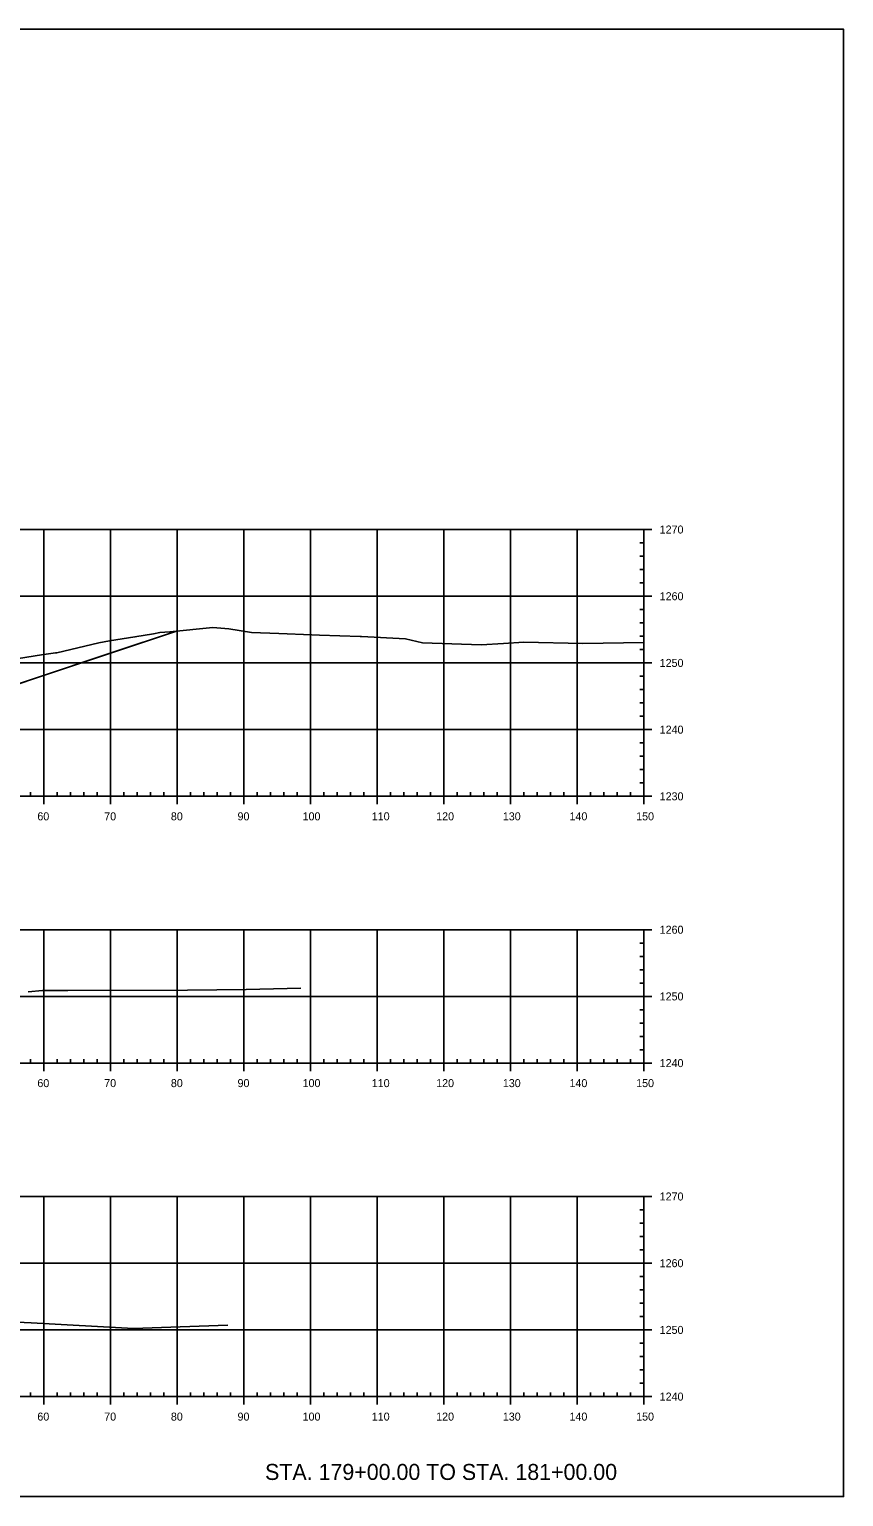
# Model space of a CAD drawing. Extents: x 659657 to 668193, y 633084 to 648639.
# Drawn here: x 667020.3 to 667142.5, y 643502.4 to 643722.4 of the extents above; entities that cross this region are included whole.
import ezdxf

# ---------------------------------------------------------------- set-up
doc = ezdxf.new("R2010")
doc.units = 0
for name, color, linetype in [('Default', 7, 'Continuous'), ('R_Axis', 7, 'Continuous'), ('R_Axis Annot', 7, 'Continuous'), ('R_Exist Surface', 7, 'Continuous'), ('R_Grid', 7, 'Continuous'), ('T_SIGNAL CONTROL CABINET', 7, 'Continuous'), ('TEMP_SIGNAL POLES', 7, 'Continuous'), ('TEMP_SIGNAL_HEAD_STAGE 5', 7, 'Continuous')]:
    doc.layers.add(name, color=color, linetype=linetype)

msp = doc.modelspace()

# ---------------------------------------------------------------- linework, layer by layer
at = {"layer": 'Default'}
for points in [[(666915.04, 643630.48), (666929.59, 643628.06), (666951.01, 643631.63), (666955.01, 643631.3), (666970.01, 643630.05), (666976.01, 643629.55), (667000.01, 643625.55), (667011.31, 643621.79), (667017.29, 643623.78), (667022.62, 643625.56), (667025, 643626.35), (667028.57, 643627.54), (667032.79, 643628.95), (667042.41, 643632.15)], [(666958.62, 643631.58), (666959.01, 643630.8), (666959.01, 643630.97), (666970.01, 643630.05), (666976.01, 643629.55), (667000.01, 643625.55), (667011.31, 643621.79), (667017.29, 643623.78), (667022.62, 643625.56), (667025, 643626.35), (667028.57, 643627.54), (667032.79, 643628.95), (667042.41, 643632.15)]]:
    msp.add_lwpolyline(points, dxfattribs=at)
at = {"layer": 'R_Axis'}
for p, q in [((667113.71, 643647.39), (667111.31, 643647.39)), ((667112.51, 643645.39), (667111.91, 643645.39)), ((667112.51, 643607.39), (667112.51, 643647.39)), ((667112.51, 643643.39), (667111.91, 643643.39)), ((667112.51, 643641.39), (667111.91, 643641.39)), ((667112.51, 643639.39), (667111.91, 643639.39)), ((667113.71, 643637.39), (667111.31, 643637.39)), ((667112.51, 643635.39), (667111.91, 643635.39)), ((667112.51, 643633.39), (667111.91, 643633.39)), ((667112.51, 643631.39), (667111.91, 643631.39)), ((667112.51, 643629.39), (667111.91, 643629.39)), ((667113.71, 643627.39), (667111.31, 643627.39)), ((667112.51, 643625.39), (667111.91, 643625.39)), ((667112.51, 643623.39), (667111.91, 643623.39)), ((667112.51, 643621.39), (667111.91, 643621.39)), ((667112.51, 643619.39), (667111.91, 643619.39)), ((667113.71, 643617.39), (667111.31, 643617.39)), ((667112.51, 643615.39), (667111.91, 643615.39)), ((667112.51, 643613.39), (667111.91, 643613.39)), ((667112.51, 643611.39), (667111.91, 643611.39)), ((667020.51, 643607.39), (667020.51, 643607.99)), ((667022.51, 643606.19), (667022.51, 643608.59)), ((667024.51, 643607.39), (667024.51, 643607.99)), ((667026.51, 643607.39), (667026.51, 643607.99)), ((667028.51, 643607.39), (667028.51, 643607.99)), ((667030.51, 643607.39), (667030.51, 643607.99)), ((667032.51, 643606.19), (667032.51, 643608.59)), ((667034.51, 643607.39), (667034.51, 643607.99)), ((667036.51, 643607.39), (667036.51, 643607.99)), ((667038.51, 643607.39), (667038.51, 643607.99)), ((667040.51, 643607.39), (667040.51, 643607.99)), ((667042.51, 643606.19), (667042.51, 643608.59)), ((667044.51, 643607.39), (667044.51, 643607.99)), ((667046.51, 643607.39), (667046.51, 643607.99)), ((667048.51, 643607.39), (667048.51, 643607.99)), ((667050.51, 643607.39), (667050.51, 643607.99)), ((667052.51, 643606.19), (667052.51, 643608.59)), ((667054.51, 643607.39), (667054.51, 643607.99)), ((667056.51, 643607.39), (667056.51, 643607.99)), ((667058.51, 643607.39), (667058.51, 643607.99)), ((667060.51, 643607.39), (667060.51, 643607.99)), ((667062.51, 643606.19), (667062.51, 643608.59)), ((667064.51, 643607.39), (667064.51, 643607.99)), ((667066.51, 643607.39), (667066.51, 643607.99)), ((667068.51, 643607.39), (667068.51, 643607.99)), ((667070.51, 643607.39), (667070.51, 643607.99)), ((667072.51, 643606.19), (667072.51, 643608.59)), ((667074.51, 643607.39), (667074.51, 643607.99)), ((667076.51, 643607.39), (667076.51, 643607.99)), ((667078.51, 643607.39), (667078.51, 643607.99)), ((667080.51, 643607.39), (667080.51, 643607.99)), ((667082.51, 643606.19), (667082.51, 643608.59)), ((667084.51, 643607.39), (667084.51, 643607.99)), ((667086.51, 643607.39), (667086.51, 643607.99)), ((667088.51, 643607.39), (667088.51, 643607.99)), ((667090.51, 643607.39), (667090.51, 643607.99)), ((667092.51, 643606.19), (667092.51, 643608.59)), ((667094.51, 643607.39), (667094.51, 643607.99)), ((667096.51, 643607.39), (667096.51, 643607.99)), ((667098.51, 643607.39), (667098.51, 643607.99)), ((667100.51, 643607.39), (667100.51, 643607.99)), ((667102.51, 643606.19), (667102.51, 643608.59)), ((667104.51, 643607.39), (667104.51, 643607.99)), ((667106.51, 643607.39), (667106.51, 643607.99)), ((667108.51, 643607.39), (667108.51, 643607.99)), ((667110.51, 643607.39), (667110.51, 643607.99)), ((667112.51, 643609.39), (667111.91, 643609.39)), ((667112.51, 643606.19), (667112.51, 643608.59)), ((666812.51, 643607.39), (667112.51, 643607.39)), ((667113.71, 643607.39), (667111.31, 643607.39)), ((667113.71, 643587.39), (667111.31, 643587.39)), ((667112.51, 643567.39), (667112.51, 643587.39)), ((667112.51, 643585.39), (667111.91, 643585.39)), ((667112.51, 643583.39), (667111.91, 643583.39)), ((667112.51, 643581.39), (667111.91, 643581.39)), ((667112.51, 643579.39), (667111.91, 643579.39)), ((667113.71, 643577.39), (667111.31, 643577.39)), ((667112.51, 643575.39), (667111.91, 643575.39)), ((667112.51, 643573.39), (667111.91, 643573.39)), ((667112.51, 643571.39), (667111.91, 643571.39)), ((667022.51, 643566.19), (667022.51, 643568.59)), ((667032.51, 643566.19), (667032.51, 643568.59)), ((667042.51, 643566.19), (667042.51, 643568.59)), ((667052.51, 643566.19), (667052.51, 643568.59)), ((667062.51, 643566.19), (667062.51, 643568.59)), ((667072.51, 643566.19), (667072.51, 643568.59)), ((667082.51, 643566.19), (667082.51, 643568.59)), ((667092.51, 643566.19), (667092.51, 643568.59)), ((667102.51, 643566.19), (667102.51, 643568.59)), ((667112.51, 643569.39), (667111.91, 643569.39)), ((667112.51, 643566.19), (667112.51, 643568.59)), ((666812.51, 643567.39), (667112.51, 643567.39)), ((667020.51, 643567.39), (667020.51, 643567.99)), ((667024.51, 643567.39), (667024.51, 643567.99)), ((667026.51, 643567.39), (667026.51, 643567.99)), ((667028.51, 643567.39), (667028.51, 643567.99)), ((667030.51, 643567.39), (667030.51, 643567.99)), ((667034.51, 643567.39), (667034.51, 643567.99)), ((667036.51, 643567.39), (667036.51, 643567.99)), ((667038.51, 643567.39), (667038.51, 643567.99)), ((667040.51, 643567.39), (667040.51, 643567.99)), ((667044.51, 643567.39), (667044.51, 643567.99)), ((667046.51, 643567.39), (667046.51, 643567.99)), ((667048.51, 643567.39), (667048.51, 643567.99)), ((667050.51, 643567.39), (667050.51, 643567.99)), ((667054.51, 643567.39), (667054.51, 643567.99)), ((667056.51, 643567.39), (667056.51, 643567.99)), ((667058.51, 643567.39), (667058.51, 643567.99)), ((667060.51, 643567.39), (667060.51, 643567.99)), ((667064.51, 643567.39), (667064.51, 643567.99)), ((667066.51, 643567.39), (667066.51, 643567.99)), ((667068.51, 643567.39), (667068.51, 643567.99)), ((667070.51, 643567.39), (667070.51, 643567.99)), ((667074.51, 643567.39), (667074.51, 643567.99)), ((667076.51, 643567.39), (667076.51, 643567.99)), ((667078.51, 643567.39), (667078.51, 643567.99)), ((667080.51, 643567.39), (667080.51, 643567.99)), ((667084.51, 643567.39), (667084.51, 643567.99)), ((667086.51, 643567.39), (667086.51, 643567.99)), ((667088.51, 643567.39), (667088.51, 643567.99)), ((667090.51, 643567.39), (667090.51, 643567.99)), ((667094.51, 643567.39), (667094.51, 643567.99)), ((667096.51, 643567.39), (667096.51, 643567.99)), ((667098.51, 643567.39), (667098.51, 643567.99)), ((667100.51, 643567.39), (667100.51, 643567.99)), ((667104.51, 643567.39), (667104.51, 643567.99)), ((667106.51, 643567.39), (667106.51, 643567.99)), ((667108.51, 643567.39), (667108.51, 643567.99)), ((667110.51, 643567.39), (667110.51, 643567.99)), ((667113.71, 643567.39), (667111.31, 643567.39)), ((667113.71, 643547.39), (667111.31, 643547.39)), ((667112.51, 643517.39), (667112.51, 643547.39)), ((667112.51, 643545.39), (667111.91, 643545.39)), ((667112.51, 643543.39), (667111.91, 643543.39)), ((667112.51, 643541.39), (667111.91, 643541.39)), ((667112.51, 643539.39), (667111.91, 643539.39)), ((667113.71, 643537.39), (667111.31, 643537.39)), ((667112.51, 643535.39), (667111.91, 643535.39)), ((667112.51, 643533.39), (667111.91, 643533.39)), ((667112.51, 643531.39), (667111.91, 643531.39)), ((667112.51, 643529.39), (667111.91, 643529.39)), ((667113.71, 643527.39), (667111.31, 643527.39)), ((667112.51, 643525.39), (667111.91, 643525.39)), ((667112.51, 643523.39), (667111.91, 643523.39)), ((667112.51, 643521.39), (667111.91, 643521.39)), ((667020.51, 643517.39), (667020.51, 643517.99)), ((667022.51, 643516.19), (667022.51, 643518.59)), ((667024.51, 643517.39), (667024.51, 643517.99)), ((667026.51, 643517.39), (667026.51, 643517.99)), ((667028.51, 643517.39), (667028.51, 643517.99)), ((667030.51, 643517.39), (667030.51, 643517.99)), ((667032.51, 643516.19), (667032.51, 643518.59)), ((667034.51, 643517.39), (667034.51, 643517.99)), ((667036.51, 643517.39), (667036.51, 643517.99)), ((667038.51, 643517.39), (667038.51, 643517.99)), ((667040.51, 643517.39), (667040.51, 643517.99)), ((667042.51, 643516.19), (667042.51, 643518.59)), ((667044.51, 643517.39), (667044.51, 643517.99)), ((667046.51, 643517.39), (667046.51, 643517.99)), ((667048.51, 643517.39), (667048.51, 643517.99)), ((667050.51, 643517.39), (667050.51, 643517.99)), ((667052.51, 643516.19), (667052.51, 643518.59)), ((667054.51, 643517.39), (667054.51, 643517.99)), ((667056.51, 643517.39), (667056.51, 643517.99)), ((667058.51, 643517.39), (667058.51, 643517.99)), ((667060.51, 643517.39), (667060.51, 643517.99)), ((667062.51, 643516.19), (667062.51, 643518.59)), ((667064.51, 643517.39), (667064.51, 643517.99)), ((667066.51, 643517.39), (667066.51, 643517.99)), ((667068.51, 643517.39), (667068.51, 643517.99)), ((667070.51, 643517.39), (667070.51, 643517.99)), ((667072.51, 643516.19), (667072.51, 643518.59)), ((667074.51, 643517.39), (667074.51, 643517.99)), ((667076.51, 643517.39), (667076.51, 643517.99)), ((667078.51, 643517.39), (667078.51, 643517.99)), ((667080.51, 643517.39), (667080.51, 643517.99)), ((667082.51, 643516.19), (667082.51, 643518.59)), ((667084.51, 643517.39), (667084.51, 643517.99)), ((667086.51, 643517.39), (667086.51, 643517.99)), ((667088.51, 643517.39), (667088.51, 643517.99)), ((667090.51, 643517.39), (667090.51, 643517.99)), ((667092.51, 643516.19), (667092.51, 643518.59)), ((667094.51, 643517.39), (667094.51, 643517.99)), ((667096.51, 643517.39), (667096.51, 643517.99)), ((667098.51, 643517.39), (667098.51, 643517.99)), ((667100.51, 643517.39), (667100.51, 643517.99)), ((667102.51, 643516.19), (667102.51, 643518.59)), ((667104.51, 643517.39), (667104.51, 643517.99)), ((667106.51, 643517.39), (667106.51, 643517.99)), ((667108.51, 643517.39), (667108.51, 643517.99)), ((667110.51, 643517.39), (667110.51, 643517.99)), ((667112.51, 643519.39), (667111.91, 643519.39)), ((667112.51, 643516.19), (667112.51, 643518.59)), ((666812.51, 643517.39), (667112.51, 643517.39)), ((667113.71, 643517.39), (667111.31, 643517.39))]:
    msp.add_line(p, q, dxfattribs=at)
at = {"layer": 'R_Exist Surface'}
for points in [[(667008.01, 643626.34), (667022.17, 643628.59), (667024.27, 643628.88), (667024.49, 643628.92), (667030.78, 643630.41), (667032.36, 643630.68), (667036.18, 643631.28), (667038.97, 643631.75), (667039.91, 643631.94), (667041.43, 643632.06), (667047.87, 643632.68), (667050.27, 643632.48), (667053.65, 643631.97), (667057.77, 643631.78), (667062.73, 643631.6), (667063.89, 643631.57), (667069.97, 643631.35), (667070.2, 643631.35), (667076.77, 643631.02), (667079.33, 643630.41), (667088.12, 643630.1), (667091.49, 643630.32), (667094.55, 643630.52), (667103.39, 643630.31), (667112.51, 643630.45)], [(667020.19, 643578.09), (667022.31, 643578.26), (667026.11, 643578.28), (667044.08, 643578.33), (667052.89, 643578.45), (667061.08, 643578.63)], [(667018.54, 643528.56), (667020.62, 643528.43), (667035.97, 643527.6), (667042.99, 643527.85), (667050.1, 643528.12)]]:
    msp.add_lwpolyline(points, dxfattribs=at)
at = {"layer": 'R_Grid'}
for p, q in [((666812.51, 643647.39), (667112.51, 643647.39)), ((667022.51, 643607.39), (667022.51, 643647.39)), ((667032.51, 643607.39), (667032.51, 643647.39)), ((667042.51, 643607.39), (667042.51, 643647.39)), ((667052.51, 643607.39), (667052.51, 643647.39)), ((667062.51, 643607.39), (667062.51, 643647.39)), ((667072.51, 643607.39), (667072.51, 643647.39)), ((667082.51, 643607.39), (667082.51, 643647.39)), ((667092.51, 643607.39), (667092.51, 643647.39)), ((667102.51, 643607.39), (667102.51, 643647.39)), ((667112.51, 643607.39), (667112.51, 643647.39)), ((666812.51, 643637.39), (667112.51, 643637.39)), ((666812.51, 643627.39), (667112.51, 643627.39)), ((666812.51, 643617.39), (667112.51, 643617.39)), ((666812.51, 643607.39), (667112.51, 643607.39)), ((666812.51, 643587.39), (667112.51, 643587.39)), ((667022.51, 643567.39), (667022.51, 643587.39)), ((667032.51, 643567.39), (667032.51, 643587.39)), ((667042.51, 643567.39), (667042.51, 643587.39)), ((667052.51, 643567.39), (667052.51, 643587.39)), ((667062.51, 643567.39), (667062.51, 643587.39)), ((667072.51, 643567.39), (667072.51, 643587.39)), ((667082.51, 643567.39), (667082.51, 643587.39)), ((667092.51, 643567.39), (667092.51, 643587.39)), ((667102.51, 643567.39), (667102.51, 643587.39)), ((667112.51, 643567.39), (667112.51, 643587.39)), ((666812.51, 643577.39), (667112.51, 643577.39)), ((666812.51, 643567.39), (667112.51, 643567.39)), ((666812.51, 643547.39), (667112.51, 643547.39)), ((667022.51, 643517.39), (667022.51, 643547.39)), ((667032.51, 643517.39), (667032.51, 643547.39)), ((667042.51, 643517.39), (667042.51, 643547.39)), ((667052.51, 643517.39), (667052.51, 643547.39)), ((667062.51, 643517.39), (667062.51, 643547.39)), ((667072.51, 643517.39), (667072.51, 643547.39)), ((667082.51, 643517.39), (667082.51, 643547.39)), ((667092.51, 643517.39), (667092.51, 643547.39)), ((667102.51, 643517.39), (667102.51, 643547.39)), ((667112.51, 643517.39), (667112.51, 643547.39)), ((666812.51, 643537.39), (667112.51, 643537.39)), ((666812.51, 643527.39), (667112.51, 643527.39)), ((666812.51, 643517.39), (667112.51, 643517.39))]:
    msp.add_line(p, q, dxfattribs=at)
at = {"layer": 'T_SIGNAL CONTROL CABINET'}
msp.add_lwpolyline([(666802.51, 643502.39), (667142.51, 643502.39), (667142.51, 643722.39), (666802.51, 643722.39)], close=True, dxfattribs=at)
at = {"layer": 'TEMP_SIGNAL_HEAD_STAGE 5'}
msp.add_lwpolyline([(666976.01, 643629.55), (667000.01, 643625.55), (667011.31, 643621.79), (667042.41, 643632.15)], dxfattribs=at)
msp.add_lwpolyline([(666976.01, 643629.55), (667000.01, 643625.55), (667011.31, 643621.79), (667042.41, 643632.15)], dxfattribs=at)

# ---------------------------------------------------------------- texts
at = {"layer": 'R_Axis Annot'}
for s, p in [('1270', (667114.91, 643646.79)), ('1260', (667114.91, 643636.79)), ('1250', (667114.91, 643626.79)), ('1240', (667114.91, 643616.79)), ('1230', (667114.91, 643606.79)), ('60', (667021.55, 643603.79)), ('70', (667031.58, 643603.79)), ('80', (667041.58, 643603.79)), ('90', (667051.58, 643603.79)), ('100', (667061.34, 643603.79)), ('110', (667071.72, 643603.79)), ('120', (667081.38, 643603.79)), ('130', (667091.38, 643603.79)), ('140', (667101.38, 643603.79)), ('150', (667111.38, 643603.79)), ('1260', (667114.91, 643586.79)), ('1250', (667114.91, 643576.79)), ('1240', (667114.91, 643566.79)), ('60', (667021.55, 643563.79)), ('70', (667031.58, 643563.79)), ('80', (667041.58, 643563.79)), ('90', (667051.58, 643563.79)), ('100', (667061.34, 643563.79)), ('110', (667071.72, 643563.79)), ('120', (667081.38, 643563.79)), ('130', (667091.38, 643563.79)), ('140', (667101.38, 643563.79)), ('150', (667111.38, 643563.79)), ('1270', (667114.91, 643546.79)), ('1260', (667114.91, 643536.79)), ('1250', (667114.91, 643526.79)), ('1240', (667114.91, 643516.79)), ('60', (667021.55, 643513.79)), ('70', (667031.58, 643513.79)), ('80', (667041.58, 643513.79)), ('90', (667051.58, 643513.79)), ('100', (667061.34, 643513.79)), ('110', (667071.72, 643513.79)), ('120', (667081.38, 643513.79)), ('130', (667091.38, 643513.79)), ('140', (667101.38, 643513.79)), ('150', (667111.38, 643513.79))]:
    msp.add_text(s, height=1.2, dxfattribs=at).set_placement(p)
at = {"layer": 'TEMP_SIGNAL POLES'}
msp.add_text('STA. 179+00.00 TO STA. 181+00.00', height=2.4, dxfattribs=at).set_placement((667055.71, 643504.89))

doc.saveas('drawing.dxf')
